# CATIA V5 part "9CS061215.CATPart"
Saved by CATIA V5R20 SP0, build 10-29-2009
Part number: 9CS061215
Revision: ANY
Definition: UNKNOWN
Nomenclature: 9CS061215
Source: Unknown
Bounding box of the stored display mesh (mm): x -5.85 to 5.85, y 0 to 15, z -6 to 6
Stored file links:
  C:\Users\Utente\Desktop\IO LAVORO\3D X SITO CF\CUMSA\3D files PW\pw060830\pw060830_ejection\9CS061215.CATPart
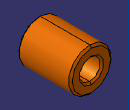
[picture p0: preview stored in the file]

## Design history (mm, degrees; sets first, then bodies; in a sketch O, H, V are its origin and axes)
Body1 "Revolución1" (main body)
  Solid1: solid without history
